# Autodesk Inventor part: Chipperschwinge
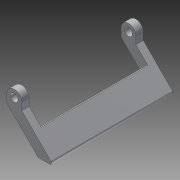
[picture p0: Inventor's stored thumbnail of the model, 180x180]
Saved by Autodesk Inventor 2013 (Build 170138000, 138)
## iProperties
Created: 2012-09
Part Number: Chipperschwinge
Material: Aluminium 6061
Document SubType Name: Modeling
Designer: rYan
Density: 2.71 g/cm^3
Mass: 14.0612 g
Surface Area: 34.4985 cm^2
Volume: 5.18864 cm^3
d0: 6,000 mm
d1: 45,00 grd
Author: rYan
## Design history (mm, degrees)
sketch "Skizze1"
  geometry: L1 (0, 0)-(17.5, 17.5); L2 (17.5, 17.5)-(17.5, 21.5); L3 (25.5, 17.015)-(8.485, 0); L4 (8.485, 0)-(0, 0); L5 (25.5, 21.5)-(25.5, 17.015); L6 (-5.1, 0)-(30.6, 0) reference; A1 r 4 centre (21.5, 21.5) between (25.5, 21.5) and (17.5, 21.5); 1 further point
  constraints: 11 end point, 2 point on circle, 2 tangent, 2 vertical, 1 centre point, 1 coincident, 1 horizontal, 1 parallel, 1 point on line
  dimensions: "d0" = 6 distance between parallel lines of L3 L1; "d1" = 45 deg angle of L4 L3; "d3" = 21.5 distance from line of A1.centre L6; "d22" = 4 radius of A1
extrude "Extrusion1" new body sketch "Skizze1" distance "d4" = 4; taper "d5" = 0 deg
sketch "Skizze2"
  geometry: L1 (0, 0)-(-17.5, 17.5) reference; L2 (-8.485, 0)-(0, 0) reference; L3 (-25.5, 17.015)-(-8.485, 0) reference; L4 (0, 0)-(-8.485, 0); L5 (-8.485, 0)-(-11.5, 3.015); L6 (-11.5, 11)-(-11, 11); L7 (-11.5, 3.015)-(-11.5, 11); L8 (-11, 11)-(0, 0); L9 (-30.891, 0)-(5.149, 0) reference
  constraints: 10 end point, 2 collinear, 2 point on line, 1 parallel, 1 perpendicular
  dimensions: "d10" = 11 distance between parallel lines of L9 L6; "d11" = 11.5 distance from line of L1.start L7
extrude "Extrusion2" join sketch "Skizze2" distance "d12" = 28.8; taper "d13" = 0 deg
mirror "Spiegeln1"
sketch "Skizze4"
  geometry: A1 r 4 centre (-21.5, -21.5) between (-25.5, -21.5) and (-17.5, -21.5) reference; 2 further points
  constraints: 1 coincident
hole "Bohrung1" sketch "Skizze4" at (-21.5, -21.5) diameter "d14" = 4.1; stored, may be unused: countersink angle "d18" = 90 deg, drill point angle "d20" = 118 deg; dims "d15" = 6, "d16" = 4, "d17" = 2, "d19" = 8
fillet "Rundung1" dims "d21" = 1
node "Volumenkörper1"
